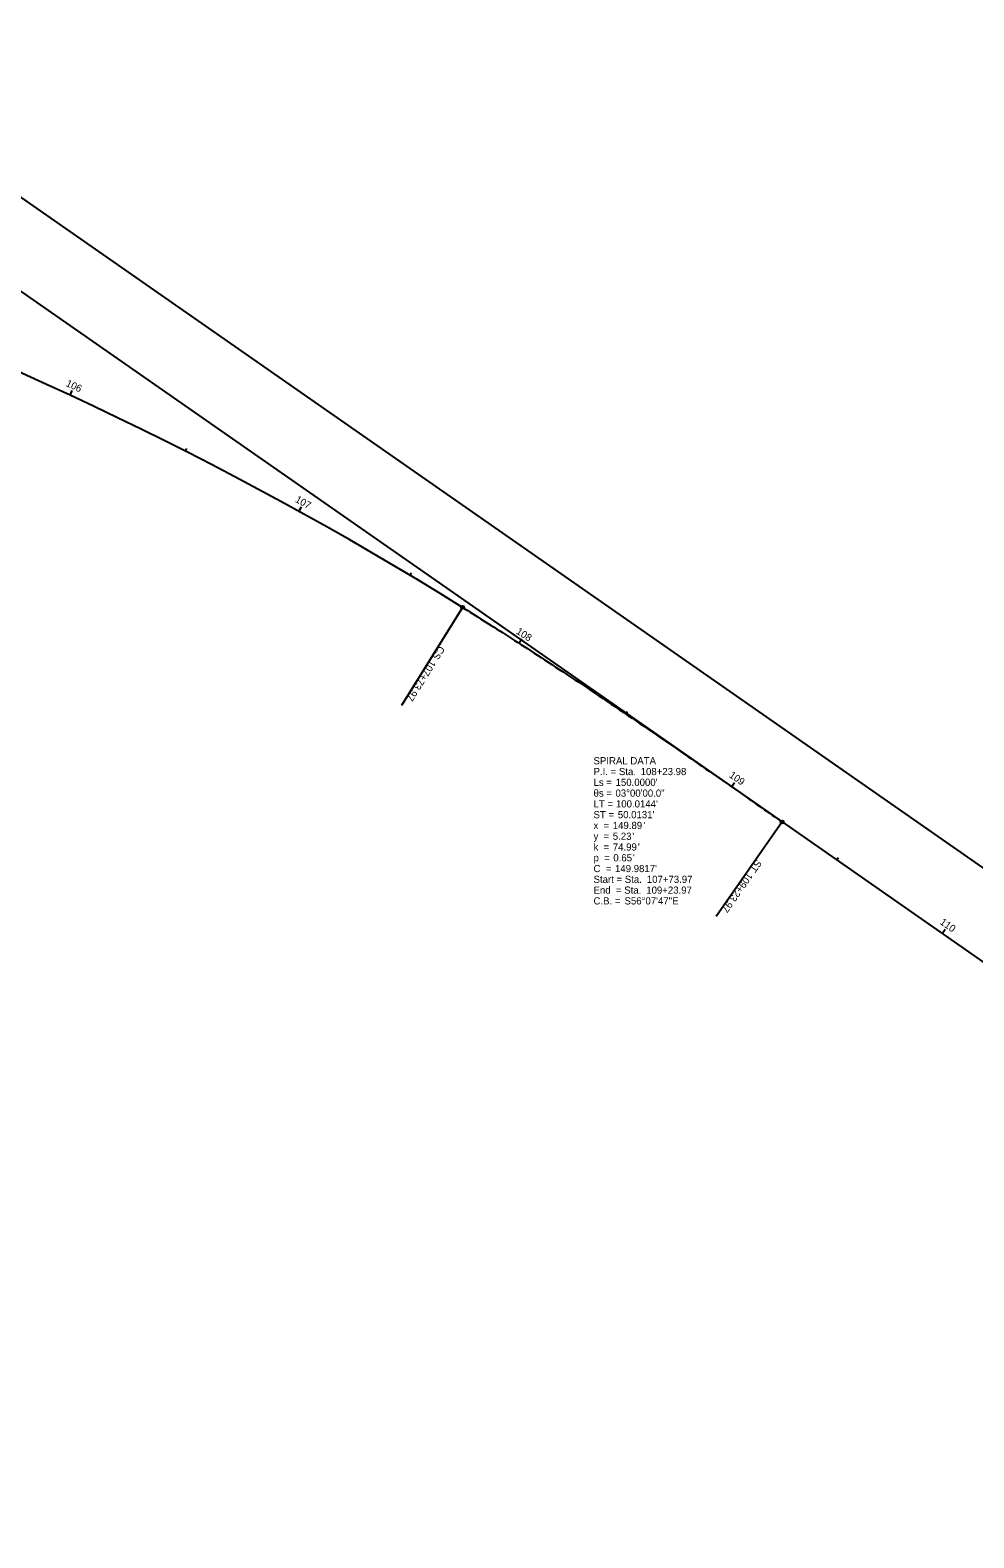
# Model space of a CAD drawing. Extents: x 2318731 to 2320621, y 732958 to 734198.
# Drawn here: x 2319901 to 2320268, y 732959 to 733546 of the extents above; entities that cross this region are included whole.
import ezdxf

# ---------------------------------------------------------------- set-up
doc = ezdxf.new("R2010")
doc.units = 0
for name, color, linetype in [('RW_X_CL_100_Cardinal_Points', 7, 'Continuous'), ('RW_X_CL_100_Stations', 7, 'Continuous'), ('RW_X_CL_500_Cardinal_Points', 7, 'Continuous'), ('RW_X_CL_500_Curve_Data', 7, 'Continuous'), ('RW_X_CL_500_Stations', 7, 'Continuous'), ('V-SURV-IPF', 7, 'Continuous'), ('V-SURV-PARL-LINE', 7, 'Continuous'), ('V-SURV-PARL-SUBL', 7, 'Continuous'), ('V-SURV-RWAY', 7, 'Continuous')]:
    doc.layers.add(name, color=color, linetype=linetype)

msp = doc.modelspace()

# ---------------------------------------------------------------- linework, layer by layer
at = {"layer": 'RW_X_CL_100_Cardinal_Points'}
for p, q in [((2320069.22, 733321.27), (2320045.46, 733283.06)), ((2320193.75, 733237.69), (2320168.02, 733200.77))]:
    msp.add_line(p, q, dxfattribs=at)
for centre in [(2320069.22, 733321.27), (2320193.75, 733237.69)]:
    msp.add_circle(centre, 0.6, dxfattribs=at)
at = {"layer": 'RW_X_CL_100_Stations'}
for p, q in [((2319916.27, 733403.94), (2319917.11, 733405.76)), ((2319961.24, 733382.09), (2319961.78, 733383.17)), ((2320005.42, 733358.69), (2320006.39, 733360.44)), ((2320048.76, 733333.76), (2320049.37, 733334.79)), ((2320091.2, 733307.34), (2320092.29, 733309.02)), ((2320132.88, 733279.72), (2320133.55, 733280.71)), ((2320174.08, 733251.38), (2320175.22, 733253.03)), ((2320215.1, 733222.81), (2320215.79, 733223.79)), ((2320256.13, 733194.22), (2320257.27, 733195.86))]:
    msp.add_line(p, q, dxfattribs=at)
at = {"layer": 'RW_X_CL_500_Cardinal_Points'}
for p, q in [((2320069.22, 733321.27), (2320045.46, 733283.06)), ((2320193.75, 733237.69), (2320168.02, 733200.77))]:
    msp.add_line(p, q, dxfattribs=at)
for centre in [(2320069.22, 733321.27), (2320193.75, 733237.69)]:
    msp.add_circle(centre, 0.6, dxfattribs=at)
at = {"layer": 'RW_X_CL_500_Stations'}
for p, q in [((2319916.27, 733403.94), (2319916.77, 733405.03)), ((2320005.42, 733358.69), (2320006, 733359.74)), ((2320091.2, 733307.34), (2320091.86, 733308.35)), ((2320174.08, 733251.38), (2320174.76, 733252.37)), ((2320256.13, 733194.22), (2320257.27, 733195.86))]:
    msp.add_line(p, q, dxfattribs=at)
at = {"layer": 'V-SURV-IPF'}
msp.add_line((2319793.43, 733516.64), (2320193.75, 733237.69), dxfattribs=at)
at = {"layer": 'V-SURV-PARL-LINE'}
msp.add_line((2319803.49, 733546.2), (2320611.23, 732983.34), dxfattribs=at)
at = {"layer": 'V-SURV-RWAY'}
msp.add_line((2320193.75, 733237.69), (2320594.07, 732958.73), dxfattribs=at)
msp.add_arc((2319312.92, 732104.82), 1432.39, 58.12986, 84.27847, dxfattribs=at)
msp.add_open_spline([(2320069.22, 733321.27), (2320074.53, 733317.97), (2320085.1, 733311.3), (2320106.09, 733297.72), (2320132.07, 733280.36), (2320157.83, 733262.67), (2320178.36, 733248.41), (2320188.62, 733241.26), (2320193.75, 733237.69)], degree=3, dxfattribs=at)

# ---------------------------------------------------------------- texts
at = {"layer": 'RW_X_CL_100_Cardinal_Points'}
for s, rotation, p in [('CS', 238.12986, (2320060.09, 733306.5)), ('107+73.97', 238.12986, (2320056.64, 733300.96)), ('ST', 235.12986, (2320183.73, 733223.23)), ('109+23.97', 235.12986, (2320180.25, 733218.24))]:
    msp.add_text(s, height=2.8, rotation=rotation, dxfattribs=at).set_placement(p)
at = {"layer": 'RW_X_CL_100_Stations'}
for s, rotation, p in [('106', 335.08865, (2319914.36, 733407.64)), ('107', 331.08865, (2320003.73, 733362.53)), ('108', 327.17899, (2320089.83, 733311.26)), ('109', 325.20646, (2320172.86, 733255.33)), ('110', 325.12986, (2320255.01, 733198.1))]:
    msp.add_text(s, height=2.8, rotation=rotation, dxfattribs=at).set_placement(p)
at = {"layer": 'RW_X_CL_500_Cardinal_Points'}
for s, rotation, p in [('CS', 238.12986, (2320060.09, 733306.5)), ('107+73.97', 238.12986, (2320056.64, 733300.96)), ('ST', 235.12986, (2320183.73, 733223.23)), ('109+23.97', 235.12986, (2320180.25, 733218.24))]:
    msp.add_text(s, height=2.8, rotation=rotation, dxfattribs=at).set_placement(p)
at = {"layer": 'RW_X_CL_500_Curve_Data'}
for s, p in [('SPIRAL DATA', (2320120.26, 733260.12)), ('P.I. = Sta. ', (2320120.26, 733255.92)), ('Ls = ', (2320120.26, 733251.72)), ("150.0000'", (2320128.85, 733251.72)), ('108+23.98', (2320138.63, 733255.92)), ('θs = ', (2320120.26, 733247.52)), ('03°00\'00.0"', (2320128.8, 733247.52)), ('LT = ', (2320120.26, 733243.32)), ("100.0144'", (2320128.99, 733243.32)), ('x  = ', (2320120.26, 733234.92)), ('ST = ', (2320120.26, 733239.12)), ('149.89', (2320127.76, 733234.92)), ("50.0131'", (2320129.72, 733239.12)), ("'", (2320139.72, 733234.92)), ('y  = ', (2320120.26, 733230.72)), ('5.23', (2320127.76, 733230.72)), ("'", (2320135.37, 733230.72)), ('k  = ', (2320120.26, 733226.52)), ('74.99', (2320127.76, 733226.52)), ('0.65', (2320127.98, 733222.32)), ("'", (2320135.59, 733222.32)), ("'", (2320137.55, 733226.52)), ('C  = ', (2320120.26, 733218.12)), ('p  = ', (2320120.26, 733222.32)), ("149.9817'", (2320128.63, 733218.12)), ('Start = Sta. ', (2320120.26, 733213.92)), ('107+73.97', (2320141.02, 733213.92)), ('C.B. = ', (2320120.26, 733205.52)), ('End  = Sta. ', (2320120.26, 733209.72)), ('S56°07\'47"E', (2320132.33, 733205.52)), ('109+23.97', (2320140.81, 733209.72))]:
    msp.add_text(s, height=2.8, dxfattribs=at).set_placement(p)
at = {"layer": 'RW_X_CL_500_Stations'}
msp.add_text('110', height=2.8, rotation=325.12986, dxfattribs=at).set_placement((2320255.01, 733198.1))
at = {"layer": 'V-SURV-PARL-SUBL'}
for s, p in [('SPIRAL DATA', (2320120.26, 733260.12)), ('P.I. = Sta. ', (2320120.26, 733255.92)), ('Ls = ', (2320120.26, 733251.72)), ("150.0000'", (2320128.85, 733251.72)), ('108+23.98', (2320138.63, 733255.92)), ('θs = ', (2320120.26, 733247.52)), ('03°00\'00.0"', (2320128.8, 733247.52)), ('LT = ', (2320120.26, 733243.32)), ("100.0144'", (2320128.99, 733243.32)), ('x  = ', (2320120.26, 733234.92)), ('ST = ', (2320120.26, 733239.12)), ('149.89', (2320127.76, 733234.92)), ("50.0131'", (2320129.72, 733239.12)), ("'", (2320139.72, 733234.92)), ('y  = ', (2320120.26, 733230.72)), ('5.23', (2320127.76, 733230.72)), ("'", (2320135.37, 733230.72)), ('k  = ', (2320120.26, 733226.52)), ('74.99', (2320127.76, 733226.52)), ('0.65', (2320127.98, 733222.32)), ("'", (2320135.59, 733222.32)), ("'", (2320137.55, 733226.52)), ('C  = ', (2320120.26, 733218.12)), ('p  = ', (2320120.26, 733222.32)), ("149.9817'", (2320128.63, 733218.12)), ('Start = Sta. ', (2320120.26, 733213.92)), ('107+73.97', (2320141.02, 733213.92)), ('C.B. = ', (2320120.26, 733205.52)), ('End  = Sta. ', (2320120.26, 733209.72)), ('S56°07\'47"E', (2320132.33, 733205.52)), ('109+23.97', (2320140.81, 733209.72))]:
    msp.add_text(s, height=2.8, dxfattribs=at).set_placement(p)

doc.saveas('drawing.dxf')
